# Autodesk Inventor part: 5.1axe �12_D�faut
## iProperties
Created: 2011-01
Part Number: 5.1axe �12_D�faut
Document SubType Name: Modeling
Designer: eric
Density: 1 g/cm^3
Mass: 17.9825 g
Surface Area: 62.2035 cm^2
Volume: 17.9825 cm^3
Author: eric
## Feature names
1. Base1
